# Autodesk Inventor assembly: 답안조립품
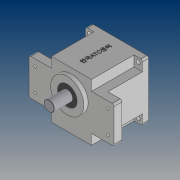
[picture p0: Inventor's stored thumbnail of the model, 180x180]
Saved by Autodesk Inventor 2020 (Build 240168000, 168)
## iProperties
Created: 2020-07
Part Number: 답안조립품
Document SubType Name: Assembly
Designer: PC312-
Author: PC312-
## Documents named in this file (10)
- C:\Users\PC312-\Desktop\700718V1007\답안조립품.iam
- C:\Users\PC312-\Desktop\700718V1007\본체.ipt
- C:\Users\PC312-\Desktop\700718V1007\커버.ipt
- C:\Users\PC312-\Desktop\700718V1007\오일 실 8 22 7.ipt
- C:\Users\PC312-\Desktop\700718V1007\오일 실 17 32 8.ipt
- C:\Users\PC312-\Desktop\700718V1007\베어링 608.ipt
- C:\Users\PC312-\Desktop\700718V1007\서브 축.ipt
- C:\Users\PC312-\Desktop\700718V1007\베어링 6003.ipt
- C:\Users\PC312-\Desktop\700718V1007\메인 축.ipt
- C:\Users\PC312-\Desktop\700718V1007\볼트 M4.ipt
